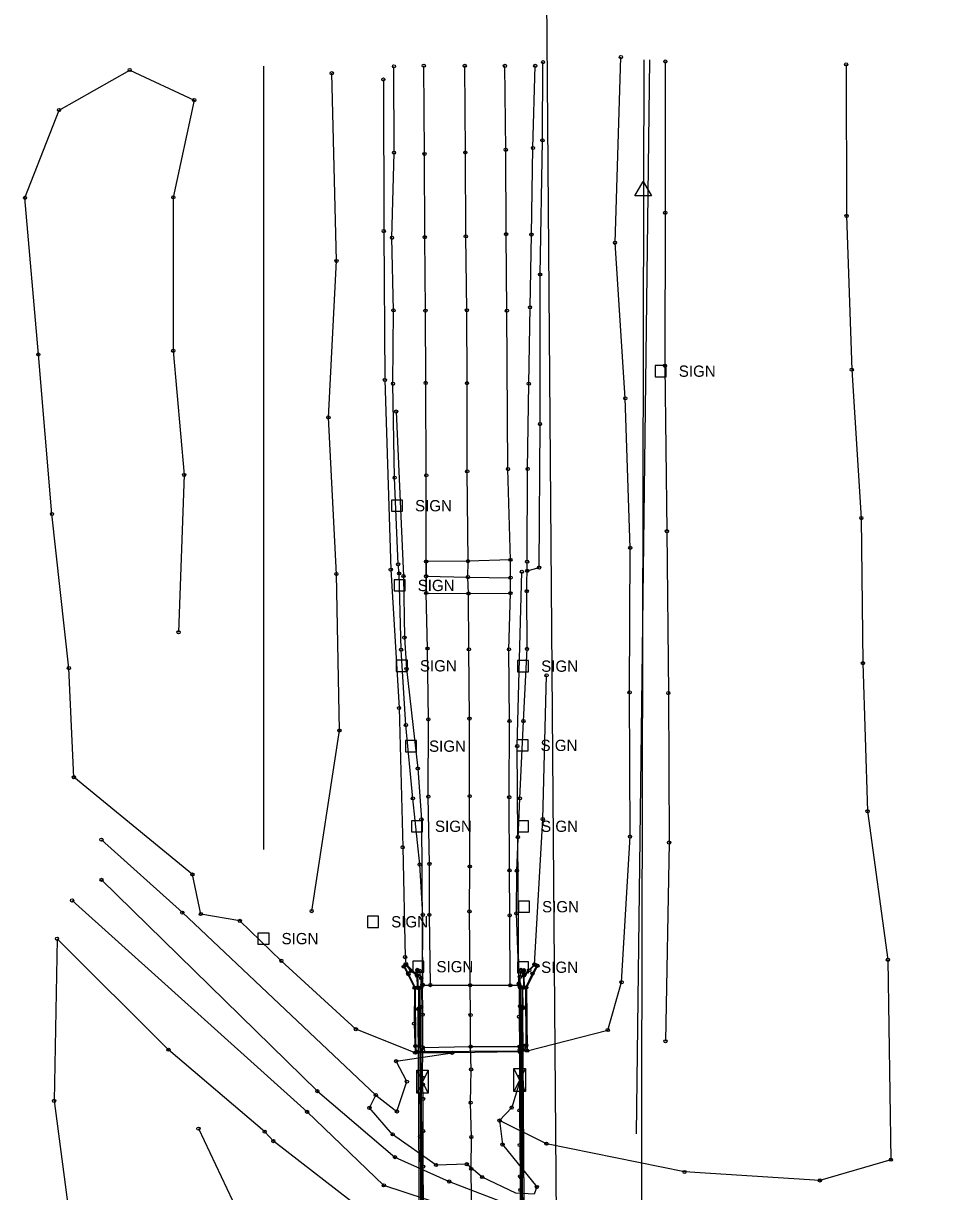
# Model space of a CAD drawing. Extents: x 23349949 to 23380641, y 6790552 to 6802878.
# Drawn here: x 23379692.7 to 23379976.3, y 6801841.9 to 6802204 of the extents above; entities that cross this region are included whole.
import ezdxf

# ---------------------------------------------------------------- set-up
doc = ezdxf.new("R2010")
doc.units = 0
for name, color, linetype in [('Bridge', 7, 'Continuous'), ('Default', 7, 'Continuous'), ('EXT_BL', 7, 'Continuous'), ('EXT_C', 7, 'Continuous'), ('EXT_CON', 7, 'Continuous'), ('EXT_D', 7, 'Continuous'), ('EXT_EP', 7, 'Continuous'), ('EXT_EW', 7, 'Continuous'), ('EXT_RIP', 7, 'Continuous'), ('EXT_SH', 7, 'Continuous'), ('EXT_SNP', 7, 'Continuous'), ('Fence', 7, 'Continuous'), ('Roadways', 7, 'Continuous'), ('Section Lines', 7, 'Continuous'), ('SurControl', 7, 'Continuous'), ('SurPointsNonDTM', 7, 'Continuous'), ('SurRoadPoints', 7, 'Continuous'), ('SurSurveyPoints', 7, 'Continuous'), ('SurUtilityStructureCell', 7, 'Continuous'), ('UtilitiesBelowGround', 7, 'Continuous')]:
    doc.layers.add(name, color=color, linetype=linetype)

msp = doc.modelspace()

# ---------------------------------------------------------------- linework, layer by layer
at = {"layer": 'Bridge'}
for points in [[(23379814.83, 6801910.41), (23379814.87, 6801905.21), (23379815.27, 6801905.15), (23379815.35, 6801898.73), (23379815.45, 6801898.69), (23379815.66, 6801859.02), (23379815.96, 6801811.56), (23379816.02, 6801793.68), (23379815.84, 6801793.6), (23379815.92, 6801787.43), (23379815.4, 6801787.33), (23379815.49, 6801782.15), (23379816.23, 6801782.19), (23379816.62, 6801784.17), (23379816.59, 6801787.37), (23379816.53, 6801793.43), (23379816.24, 6801840.68), (23379815.98, 6801886.75), (23379815.91, 6801899.2), (23379815.94, 6801905.19), (23379815.96, 6801908.06), (23379815.42, 6801910.39)], [(23379848.31, 6801782.28), (23379848.38, 6801787.45), (23379847.85, 6801787.53), (23379847.84, 6801793.59), (23379847.64, 6801793.6), (23379847.49, 6801828.75), (23379847.2, 6801874.28), (23379847.04, 6801899.2), (23379847.23, 6801899.24), (23379847.26, 6801905.19), (23379847.75, 6801905.3), (23379847.7, 6801910.43), (23379846.98, 6801910.4), (23379846.55, 6801908.46), (23379846.57, 6801905.18), (23379846.59, 6801899.38), (23379846.88, 6801846.3), (23379847.19, 6801793.54), (23379847.21, 6801787.57), (23379847.15, 6801784.62), (23379847.64, 6801782.32)]]:
    msp.add_lwpolyline(points, close=True, dxfattribs=at)
at = {"layer": 'Default'}
for points in [[(23379808.2, 6802083.67), (23379810.46, 6802032.68), (23379810.75, 6802013.63), (23379811.41, 6802003.93), (23379814.89, 6801973.06), (23379816.03, 6801957.26), (23379816.33, 6801906.07)], [(23379846.2, 6801906.45), (23379845.91, 6801951.79), (23379845.72, 6801979.99), (23379847.13, 6802034.03)], [(23379816.63, 6801838.44), (23379816.55, 6801849.66), (23379816.55, 6801860.68), (23379816.53, 6801870.67), (23379816.45, 6801875.1), (23379816.34, 6801877.26), (23379816.43, 6801886.6), (23379816.42, 6801896.78), (23379816.38, 6801905.94), (23379831.13, 6801905.9), (23379846.32, 6801905.86), (23379846.3, 6801896.12), (23379846.42, 6801886.87), (23379846.44, 6801877.59), (23379846.46, 6801875.29), (23379846.43, 6801867.11), (23379846.48, 6801856.38), (23379846.57, 6801846.67), (23379846.64, 6801837.15)], [(23379831.81, 6801786.36), (23379831.76, 6801794.46), (23379831.79, 6801805.32), (23379831.69, 6801814.45), (23379831.67, 6801823.15), (23379831.62, 6801831.78), (23379831.56, 6801840.02), (23379831.43, 6801848.98), (23379831.5, 6801858.83), (23379831.27, 6801869.49), (23379831.42, 6801879.79), (23379831.28, 6801886.87), (23379831.24, 6801896.67), (23379831.13, 6801905.9)], [(23379815.61, 6801793.82), (23379815.02, 6801898.51)], [(23379848.16, 6801793.83), (23379847.48, 6801898.81)]]:
    msp.add_lwpolyline(points, dxfattribs=at)
at = {"layer": 'EXT_BL'}
for points in [[(23379848.79, 6801885.6), (23379873.76, 6801892.01), (23379878.05, 6801906.81), (23379880.66, 6801951.96), (23379880.53, 6801996.62), (23379880.73, 6802041.44), (23379879.2, 6802087.78), (23379876.02, 6802136), (23379877.85, 6802193.52)], [(23379708.33, 6801970.36), (23379706.77, 6802004.18), (23379701.54, 6802051.94), (23379697.31, 6802101.37), (23379693.17, 6802149.91), (23379703.71, 6802177.13), (23379725.61, 6802189.53), (23379745.62, 6802180.21), (23379739.14, 6802150.07), (23379739.12, 6802102.52), (23379742.49, 6802064.02), (23379740.76, 6802015.29)], [(23379947.64, 6802191.27), (23379947.77, 6802144.32), (23379949.39, 6802096.65), (23379952.33, 6802050.65), (23379952.83, 6802005.7), (23379954.28, 6801959.8), (23379960.57, 6801913.79), (23379961.48, 6801851.82)], [(23379782.01, 6801928.86), (23379790.6, 6801984.83), (23379789.66, 6802033.32), (23379787.19, 6802081.87), (23379789.71, 6802130.34), (23379788.23, 6802188.53)], [(23379804.23, 6802186.59), (23379804.35, 6802139.62), (23379804.71, 6802093.47), (23379806.52, 6802034.68), (23379809.08, 6801991.82), (23379810.21, 6801948.66), (23379810.97, 6801914.62), (23379811.16, 6801912.47), (23379814.69, 6801908.96), (23379814.74, 6801910.64)], [(23379851.04, 6801912.36), (23379853.61, 6801957.37), (23379854.81, 6802001.92)], [(23379811.16, 6801912.47), (23379810.52, 6801911.65), (23379813.89, 6801905.08), (23379813.75, 6801893.97), (23379814.06, 6801884.98), (23379795.7, 6801892.25), (23379772.6, 6801913.46), (23379759.75, 6801925.83), (23379747.68, 6801927.96), (23379745.07, 6801940.21), (23379708.33, 6801970.36)], [(23379703.1, 6801920.29), (23379702.18, 6801870.03), (23379709, 6801818.22), (23379709.48, 6801768.84), (23379709.92, 6801712.49), (23379709.34, 6801662.19), (23379712.14, 6801615.26), (23379714.4, 6801568.49), (23379697.04, 6801486.66)], [(23379776.48, 6801800.93), (23379784.04, 6801807.41), (23379794.71, 6801819.65), (23379798.43, 6801823.96), (23379798.13, 6801835.82), (23379770.13, 6801857.58), (23379767.46, 6801860.5), (23379737.65, 6801885.91), (23379703.1, 6801920.29)], [(23379846.86, 6801910.65), (23379847.81, 6801910.54), (23379847.99, 6801909.27), (23379851.04, 6801912.36), (23379851.96, 6801911.92), (23379848.54, 6801905.19), (23379848.79, 6801885.6)], [(23379816.38, 6801905.94), (23379818.79, 6801905.94), (23379831.13, 6801905.9), (23379843.57, 6801905.87), (23379846.32, 6801905.86)], [(23379848.79, 6801885.6), (23379846.53, 6801885.2), (23379825.53, 6801884.97), (23379814.06, 6801884.98)], [(23379816.43, 6801886.6), (23379831.28, 6801886.87), (23379846.42, 6801886.87)], [(23379961.48, 6801851.82), (23379939.49, 6801845.38), (23379897.54, 6801848.01), (23379854.77, 6801856.78), (23379840.23, 6801863.95)], [(23379746.93, 6801861.44), (23379757.46, 6801839.17), (23379757.68, 6801821.63), (23379757.83, 6801766.85), (23379758.62, 6801712.77), (23379758.42, 6801663.1), (23379760.97, 6801616.65), (23379762.46, 6801572), (23379761.99, 6801495.88)]]:
    msp.add_lwpolyline(points, dxfattribs=at)
at = {"layer": 'EXT_C'}
msp.add_lwpolyline([(23379831.13, 6801905.9), (23379830.91, 6801928.76), (23379831, 6801942.69), (23379830.96, 6801964.48), (23379830.9, 6801988.52), (23379830.73, 6802009.98), (23379830.63, 6802027.3), (23379830.42, 6802032.38), (23379830.46, 6802037.32), (23379830.22, 6802065.15), (23379830.16, 6802092.47), (23379830.1, 6802115.06), (23379829.77, 6802137.98), (23379829.63, 6802163.97), (23379829.45, 6802190.83)], dxfattribs=at)
at = {"layer": 'EXT_CON'}
for points in [[(23379817.5, 6802027.44), (23379830.63, 6802027.3), (23379843.61, 6802027.39), (23379843.65, 6802032.19), (23379843.63, 6802037.73), (23379830.46, 6802037.32), (23379817.47, 6802037.21), (23379817.46, 6802032.63)], [(23379811.27, 6801912.26), (23379810.73, 6801911.79), (23379811.93, 6801909.5), (23379811.99, 6801909.33), (23379814.09, 6801905.13), (23379814.15, 6801887.06), (23379815.46, 6801887.02), (23379815.24, 6801898.63), (23379815.25, 6801905.04), (23379814.79, 6801905.05), (23379814.73, 6801908.79), (23379812.86, 6801910.29)], [(23379851.25, 6801912.2), (23379849.42, 6801910.52), (23379847.79, 6801908.92), (23379847.84, 6801905.22), (23379847.39, 6801905.09), (23379847.44, 6801899.13), (23379847.23, 6801899.07), (23379847.28, 6801887.24), (23379848.49, 6801887.27), (23379848.42, 6801905.14), (23379850.44, 6801909.48), (23379851.76, 6801911.95)]]:
    msp.add_lwpolyline(points, close=True, dxfattribs=at)
msp.add_lwpolyline([(23379848.49, 6801887.27), (23379848.2, 6801886.09), (23379846.98, 6801885.47), (23379814.56, 6801885.25), (23379814.15, 6801887.06)], dxfattribs=at)
at = {"layer": 'EXT_D'}
for p, q in [((23379886.67, 6802192.7), (23379882.56, 6801859.85)), ((23379767.1, 6802190.67), (23379767.1, 6801947.93))]:
    msp.add_line(p, q, dxfattribs=at)
msp.add_lwpolyline([(23379716.88, 6801938.56), (23379783.77, 6801873.05), (23379807.83, 6801852.6), (23379824.65, 6801845.04), (23379844.27, 6801837.55), (23379849.69, 6801837.18), (23379906.39, 6801815.92), (23379976.3, 6801820.96)], dxfattribs=at)
at = {"layer": 'EXT_EP'}
for points in [[(23379818.79, 6801905.94), (23379818.48, 6801927.7), (23379818.49, 6801943.5), (23379818.15, 6801964.35), (23379818.17, 6801988.26), (23379817.91, 6802010.25), (23379817.5, 6802027.44), (23379817.46, 6802032.63), (23379817.47, 6802037.21), (23379817.54, 6802063.91), (23379817.34, 6802092.56), (23379817.26, 6802114.95), (23379817.06, 6802137.73), (23379816.98, 6802163.51), (23379816.74, 6802190.86)], [(23379843.57, 6801905.87), (23379843.38, 6801927.53), (23379843.31, 6801941.48), (23379843.22, 6801964.14), (23379843.31, 6801987.77), (23379843.15, 6802009.98), (23379843.61, 6802027.39), (23379843.65, 6802032.19), (23379843.63, 6802037.73), (23379842.84, 6802065.84), (23379842.5, 6802114.94), (23379842.26, 6802138.66), (23379842.16, 6802164.82), (23379841.88, 6802190.81)]]:
    msp.add_lwpolyline(points, dxfattribs=at)
at = {"layer": 'EXT_EW'}
for points in [[(23379801.87, 6801871.86), (23379741.93, 6801928.39), (23379716.85, 6801951)], [(23379970.15, 6801808.32), (23379894.32, 6801809.09), (23379857.26, 6801826.44), (23379804.4, 6801843.87), (23379780.59, 6801866.66), (23379707.76, 6801932.18)]]:
    msp.add_lwpolyline(points, dxfattribs=at)
at = {"layer": 'EXT_RIP'}
msp.add_lwpolyline([(23379846.86, 6801877.14), (23379844, 6801867.97), (23379840.23, 6801863.95), (23379841.16, 6801856.51), (23379851.79, 6801843.36), (23379850.97, 6801841.13), (23379845.29, 6801841.41), (23379834.85, 6801846.44), (23379830.07, 6801850.42), (23379820.55, 6801850.16), (23379807.1, 6801859.67), (23379799.92, 6801867.87), (23379801.87, 6801871.86), (23379808.43, 6801866.75), (23379811.52, 6801876.01), (23379808.2, 6801882.34), (23379825.53, 6801884.97)], dxfattribs=at)
at = {"layer": 'EXT_SH'}
for points in [[(23379816.38, 6801905.94), (23379816.45, 6801927.66), (23379815.49, 6801943.29), (23379813.39, 6801963.81), (23379811.21, 6801986.5), (23379809.71, 6802009.88), (23379809.13, 6802033.49), (23379808.8, 6802036.34), (23379807.72, 6802063.18), (23379807.2, 6802092.28), (23379807.34, 6802115.05), (23379806.89, 6802137.54), (23379807.53, 6802163.9), (23379807.52, 6802190.66)], [(23379846.32, 6801905.86), (23379845.46, 6801928.13), (23379845.62, 6801941.37), (23379846.56, 6801963.82), (23379847.63, 6801987.74), (23379848.75, 6802010.11), (23379848.67, 6802028.02), (23379848.77, 6802037.15), (23379848.93, 6802065.92), (23379849.29, 6802092.32), (23379849.67, 6802115.98), (23379850.12, 6802138.54), (23379850.59, 6802165.37), (23379851.28, 6802190.83)]]:
    msp.add_lwpolyline(points, dxfattribs=at)
at = {"layer": 'EXT_SNP'}
msp.add_lwpolyline([(23379848.8, 6802034.32), (23379852.48, 6802035.32), (23379852.77, 6802079.79), (23379852.81, 6802126.15), (23379853.52, 6802167.72), (23379853.69, 6802191.96)], dxfattribs=at)
at = {"layer": 'Fence'}
msp.add_lwpolyline([(23379891.6, 6802192.17), (23379891.58, 6802145.28), (23379891.49, 6802097.86), (23379892.08, 6802046.58), (23379892.54, 6801996.42), (23379892.76, 6801950.09), (23379891.65, 6801888.51)], dxfattribs=at)
at = {"layer": 'Roadways'}
msp.add_lwpolyline([(23379817.46, 6802032.63), (23379830.42, 6802032.38), (23379843.65, 6802032.19)], dxfattribs=at)
at = {"layer": 'Section Lines'}
msp.add_line((23379862.42, 6801260.03), (23379853.19, 6802427.68), dxfattribs=at)
at = {"layer": 'SurControl'}
msp.add_lwpolyline([(23379884.73, 6802154.99), (23379887.28, 6802150.58), (23379882.18, 6802150.58)], close=True, dxfattribs=at)
at = {"layer": 'SurPointsNonDTM'}
for centre in [(23379891.6, 6802192.17), (23379891.58, 6802145.28), (23379891.49, 6802097.86), (23379808.2, 6802083.67), (23379892.08, 6802046.58), (23379810.46, 6802032.68), (23379817.46, 6802032.63), (23379847.13, 6802034.03), (23379830.42, 6802032.38), (23379843.65, 6802032.19), (23379810.75, 6802013.63), (23379811.41, 6802003.93), (23379892.54, 6801996.42), (23379845.72, 6801979.99), (23379814.89, 6801973.06), (23379816.03, 6801957.26), (23379845.91, 6801951.79), (23379892.76, 6801950.09), (23379814.83, 6801910.41), (23379814.83, 6801910.41), (23379815.42, 6801910.39), (23379846.98, 6801910.4), (23379847.7, 6801910.43), (23379815.96, 6801908.06), (23379816.33, 6801906.07), (23379816.38, 6801905.94), (23379831.13, 6801905.9), (23379831.13, 6801905.9), (23379846.2, 6801906.45), (23379846.32, 6801905.86), (23379846.55, 6801908.46), (23379814.87, 6801905.21), (23379815.27, 6801905.15), (23379815.94, 6801905.19), (23379846.57, 6801905.18), (23379847.26, 6801905.19), (23379847.75, 6801905.3), (23379815.35, 6801898.73), (23379815.45, 6801898.69), (23379815.91, 6801899.2), (23379846.59, 6801899.38), (23379847.04, 6801899.2), (23379847.23, 6801899.24), (23379847.48, 6801898.81), (23379815.02, 6801898.51), (23379816.42, 6801896.78), (23379831.24, 6801896.67), (23379846.3, 6801896.12), (23379891.65, 6801888.51), (23379815.98, 6801886.75), (23379816.43, 6801886.6), (23379816.49, 6801885.72), (23379831.28, 6801886.87), (23379846.42, 6801886.87), (23379846.45, 6801885.86), (23379816.34, 6801877.26), (23379831.42, 6801879.79), (23379846.44, 6801877.59), (23379816.45, 6801875.1), (23379846.46, 6801875.29), (23379847.2, 6801874.28), (23379816.53, 6801870.67), (23379831.27, 6801869.49), (23379846.43, 6801867.11), (23379815.66, 6801859.02), (23379816.55, 6801860.68), (23379831.5, 6801858.83), (23379846.48, 6801856.38), (23379816.55, 6801849.66), (23379831.43, 6801848.98), (23379846.57, 6801846.67), (23379846.88, 6801846.3), (23379846.67, 6801842.43)]:
    msp.add_circle(centre, 0.5, dxfattribs=at)
at = {"layer": 'SurRoadPoints'}
for points in [[(23379890.17, 6802094.49), (23379890.17, 6802094.49), (23379891.89, 6802094.49), (23379891.89, 6802097.91), (23379888.46, 6802097.91), (23379888.46, 6802094.49), (23379890.17, 6802094.49)], [(23379808.44, 6802052.78), (23379808.44, 6802052.78), (23379810.15, 6802052.78), (23379810.15, 6802056.21), (23379806.72, 6802056.21), (23379806.72, 6802052.78), (23379808.44, 6802052.78)], [(23379809.25, 6802028.08), (23379809.25, 6802028.08), (23379810.97, 6802028.08), (23379810.97, 6802031.51), (23379807.54, 6802031.51), (23379807.54, 6802028.08), (23379809.25, 6802028.08)], [(23379809.94, 6802003.17), (23379809.94, 6802003.17), (23379811.66, 6802003.17), (23379811.66, 6802006.6), (23379808.23, 6802006.6), (23379808.23, 6802003.17), (23379809.94, 6802003.17)], [(23379847.53, 6802003.06), (23379847.53, 6802003.06), (23379849.25, 6802003.06), (23379849.25, 6802006.49), (23379845.82, 6802006.49), (23379845.82, 6802003.06), (23379847.53, 6802003.06)], [(23379812.77, 6801978.26), (23379812.77, 6801978.26), (23379814.48, 6801978.26), (23379814.48, 6801981.69), (23379811.06, 6801981.69), (23379811.06, 6801978.26), (23379812.77, 6801978.26)], [(23379847.33, 6801978.52), (23379847.33, 6801978.52), (23379849.05, 6801978.52), (23379849.05, 6801981.94), (23379845.62, 6801981.94), (23379845.62, 6801978.52), (23379847.33, 6801978.52)], [(23379814.62, 6801953.44), (23379814.62, 6801953.44), (23379816.34, 6801953.44), (23379816.34, 6801956.86), (23379812.91, 6801956.86), (23379812.91, 6801953.44), (23379814.62, 6801953.44)], [(23379847.49, 6801953.44), (23379847.49, 6801953.44), (23379849.21, 6801953.44), (23379849.21, 6801956.86), (23379845.78, 6801956.86), (23379845.78, 6801953.44), (23379847.49, 6801953.44)], [(23379847.81, 6801928.51), (23379847.81, 6801928.51), (23379849.52, 6801928.51), (23379849.52, 6801931.94), (23379846.1, 6801931.94), (23379846.1, 6801928.51), (23379847.81, 6801928.51)], [(23379801.05, 6801923.83), (23379801.05, 6801923.83), (23379802.76, 6801923.83), (23379802.76, 6801927.26), (23379799.34, 6801927.26), (23379799.34, 6801923.83), (23379801.05, 6801923.83)], [(23379767.08, 6801918.63), (23379767.08, 6801918.63), (23379768.79, 6801918.63), (23379768.79, 6801922.06), (23379765.36, 6801922.06), (23379765.36, 6801918.63), (23379767.08, 6801918.63)], [(23379815.08, 6801909.93), (23379815.08, 6801909.93), (23379816.79, 6801909.93), (23379816.79, 6801913.36), (23379813.36, 6801913.36), (23379813.36, 6801909.93), (23379815.08, 6801909.93)], [(23379847.53, 6801909.75), (23379847.53, 6801909.75), (23379849.24, 6801909.75), (23379849.24, 6801913.18), (23379845.81, 6801913.18), (23379845.81, 6801909.75), (23379847.53, 6801909.75)]]:
    msp.add_lwpolyline(points, dxfattribs=at)
at = {"layer": 'SurSurveyPoints'}
for centre in [(23379853.69, 6802191.96), (23379877.85, 6802193.52), (23379725.61, 6802189.53), (23379788.23, 6802188.53), (23379807.52, 6802190.66), (23379816.74, 6802190.86), (23379829.45, 6802190.83), (23379841.88, 6802190.81), (23379851.28, 6802190.83), (23379947.64, 6802191.27), (23379804.23, 6802186.59), (23379745.62, 6802180.21), (23379703.71, 6802177.13), (23379853.52, 6802167.72), (23379807.53, 6802163.9), (23379816.98, 6802163.51), (23379829.63, 6802163.97), (23379842.16, 6802164.82), (23379850.59, 6802165.37), (23379693.17, 6802149.91), (23379739.14, 6802150.07), (23379947.77, 6802144.32), (23379804.35, 6802139.62), (23379817.06, 6802137.73), (23379829.77, 6802137.98), (23379842.26, 6802138.66), (23379850.12, 6802138.54), (23379806.89, 6802137.54), (23379876.02, 6802136), (23379789.71, 6802130.34), (23379852.81, 6802126.15), (23379849.67, 6802115.98), (23379807.34, 6802115.05), (23379817.26, 6802114.95), (23379830.1, 6802115.06), (23379842.5, 6802114.94), (23379697.31, 6802101.37), (23379739.12, 6802102.52), (23379949.39, 6802096.65), (23379804.71, 6802093.47), (23379807.2, 6802092.28), (23379817.34, 6802092.56), (23379830.16, 6802092.47), (23379849.29, 6802092.32), (23379879.2, 6802087.78), (23379787.19, 6802081.87), (23379852.77, 6802079.79), (23379842.84, 6802065.84), (23379848.93, 6802065.92), (23379742.49, 6802064.02), (23379807.72, 6802063.18), (23379817.54, 6802063.91), (23379830.22, 6802065.15), (23379701.54, 6802051.94), (23379952.33, 6802050.65), (23379880.73, 6802041.44), (23379808.8, 6802036.34), (23379817.47, 6802037.21), (23379817.47, 6802037.21), (23379830.46, 6802037.32), (23379830.46, 6802037.32), (23379843.63, 6802037.73), (23379843.63, 6802037.73), (23379848.77, 6802037.15), (23379789.66, 6802033.32), (23379806.52, 6802034.68), (23379809.13, 6802033.49), (23379817.46, 6802032.63), (23379817.46, 6802032.63), (23379848.8, 6802034.32), (23379852.48, 6802035.32), (23379830.42, 6802032.38), (23379843.65, 6802032.19), (23379843.65, 6802032.19), (23379817.5, 6802027.44), (23379817.5, 6802027.44), (23379817.5, 6802027.44), (23379830.63, 6802027.3), (23379830.63, 6802027.3), (23379843.61, 6802027.39), (23379843.61, 6802027.39), (23379848.67, 6802028.02), (23379740.76, 6802015.29), (23379809.71, 6802009.88), (23379817.91, 6802010.25), (23379830.73, 6802009.98), (23379843.15, 6802009.98), (23379848.75, 6802010.11), (23379706.77, 6802004.18), (23379952.83, 6802005.7), (23379854.81, 6802001.92), (23379880.53, 6801996.62), (23379809.08, 6801991.82), (23379811.21, 6801986.5), (23379818.17, 6801988.26), (23379830.9, 6801988.52), (23379843.31, 6801987.77), (23379847.63, 6801987.74), (23379790.6, 6801984.83), (23379708.33, 6801970.36), (23379708.33, 6801970.36), (23379813.39, 6801963.81), (23379818.15, 6801964.35), (23379830.96, 6801964.48), (23379843.22, 6801964.14), (23379846.56, 6801963.82), (23379853.61, 6801957.37), (23379954.28, 6801959.8), (23379716.85, 6801951), (23379880.66, 6801951.96), (23379810.21, 6801948.66), (23379815.49, 6801943.29), (23379818.49, 6801943.5), (23379831, 6801942.69), (23379716.88, 6801938.56), (23379745.07, 6801940.21), (23379843.31, 6801941.48), (23379845.62, 6801941.37), (23379707.76, 6801932.18), (23379741.93, 6801928.39), (23379747.68, 6801927.96), (23379782.01, 6801928.86), (23379816.45, 6801927.66), (23379818.48, 6801927.7), (23379830.91, 6801928.76), (23379845.46, 6801928.13), (23379759.75, 6801925.83), (23379843.38, 6801927.53), (23379703.1, 6801920.29), (23379703.1, 6801920.29), (23379772.6, 6801913.46), (23379810.97, 6801914.62), (23379960.57, 6801913.79), (23379810.52, 6801911.65), (23379810.73, 6801911.79), (23379811.16, 6801912.47), (23379811.16, 6801912.47), (23379811.27, 6801912.26), (23379811.27, 6801912.26), (23379811.93, 6801909.5), (23379812.86, 6801910.29), (23379814.74, 6801910.64), (23379846.86, 6801910.65), (23379847.81, 6801910.54), (23379849.42, 6801910.52), (23379850.44, 6801909.48), (23379851.04, 6801912.36), (23379851.04, 6801912.36), (23379851.25, 6801912.2), (23379851.25, 6801912.2), (23379851.25, 6801912.2), (23379851.76, 6801911.95), (23379851.96, 6801911.92), (23379811.99, 6801909.33), (23379814.69, 6801908.96), (23379814.73, 6801908.79), (23379816.38, 6801905.94), (23379816.38, 6801905.94), (23379818.79, 6801905.94), (23379818.79, 6801905.94), (23379831.13, 6801905.9), (23379831.13, 6801905.9), (23379843.57, 6801905.87), (23379843.57, 6801905.87), (23379846.32, 6801905.86), (23379846.32, 6801905.86), (23379847.79, 6801908.92), (23379847.99, 6801909.27), (23379878.05, 6801906.81), (23379813.89, 6801905.08), (23379814.09, 6801905.13), (23379814.79, 6801905.05), (23379815.25, 6801905.04), (23379847.39, 6801905.09), (23379847.84, 6801905.22), (23379848.42, 6801905.14), (23379848.54, 6801905.19), (23379815.24, 6801898.63), (23379847.23, 6801899.07), (23379847.44, 6801899.13), (23379795.7, 6801892.25), (23379813.75, 6801893.97), (23379873.76, 6801892.01), (23379737.65, 6801885.91), (23379814.06, 6801884.98), (23379814.06, 6801884.98), (23379814.15, 6801887.06), (23379814.15, 6801887.06), (23379814.56, 6801885.25), (23379815.46, 6801887.02), (23379816.43, 6801886.6), (23379825.53, 6801884.97), (23379825.53, 6801884.97), (23379831.28, 6801886.87), (23379846.42, 6801886.87), (23379846.53, 6801885.2), (23379846.98, 6801885.47), (23379847.28, 6801887.24), (23379848.2, 6801886.09), (23379848.49, 6801887.27), (23379848.49, 6801887.27), (23379848.79, 6801885.6), (23379848.79, 6801885.6), (23379848.79, 6801885.6), (23379808.2, 6801882.34), (23379846.86, 6801877.14), (23379811.52, 6801876.01), (23379702.18, 6801870.03), (23379783.77, 6801873.05), (23379801.87, 6801871.86), (23379801.87, 6801871.86), (23379780.59, 6801866.66), (23379799.92, 6801867.87), (23379808.43, 6801866.75), (23379844, 6801867.97), (23379840.23, 6801863.95), (23379840.23, 6801863.95), (23379746.93, 6801861.44), (23379767.46, 6801860.5), (23379807.1, 6801859.67), (23379770.13, 6801857.58), (23379841.16, 6801856.51), (23379854.77, 6801856.78), (23379807.83, 6801852.6), (23379961.48, 6801851.82), (23379961.48, 6801851.82), (23379820.55, 6801850.16), (23379830.07, 6801850.42), (23379897.54, 6801848.01), (23379824.65, 6801845.04), (23379834.85, 6801846.44), (23379939.49, 6801845.38), (23379804.4, 6801843.87), (23379851.79, 6801843.36)]:
    msp.add_circle(centre, 0.5, dxfattribs=at)
at = {"layer": 'SurUtilityStructureCell'}
for points in [[(23379818.15, 6801872.41), (23379814.55, 6801872.41), (23379814.55, 6801879.61), (23379818.15, 6801879.61)], [(23379848.28, 6801872.91), (23379844.68, 6801872.91), (23379844.68, 6801880.11), (23379848.28, 6801880.11)]]:
    msp.add_lwpolyline(points, close=True, dxfattribs=at)
for points in [[(23379818.15, 6801872.41), (23379814.55, 6801879.61), (23379818.15, 6801879.61), (23379814.55, 6801872.41)], [(23379848.28, 6801872.91), (23379844.68, 6801880.11), (23379848.28, 6801880.11), (23379844.68, 6801872.91)]]:
    msp.add_lwpolyline(points, dxfattribs=at)
at = {"layer": 'UtilitiesBelowGround'}
for p, q in [((23379884.91, 6802151.91), (23379885, 6802192.69)), ((23379884.28, 6801871.88), (23379884.91, 6802151.91)), ((23379884.41, 6801592.39), (23379884.28, 6801871.88))]:
    msp.add_line(p, q, dxfattribs=at)

# ---------------------------------------------------------------- texts
at = {"layer": 'SurRoadPoints'}
for p in [(23379895.78, 6802094.45), (23379814.04, 6802052.75), (23379814.86, 6802028.04), (23379815.55, 6802003.13), (23379853.14, 6802003.03), (23379818.38, 6801978.23), (23379852.94, 6801978.48), (23379820.23, 6801953.4), (23379853.1, 6801953.4), (23379853.41, 6801928.48), (23379806.65, 6801923.8), (23379772.68, 6801918.59), (23379820.68, 6801909.89), (23379853.13, 6801909.71)]:
    msp.add_text('SIGN', height=3.498, dxfattribs=at).set_placement(p)

doc.saveas('drawing.dxf')
